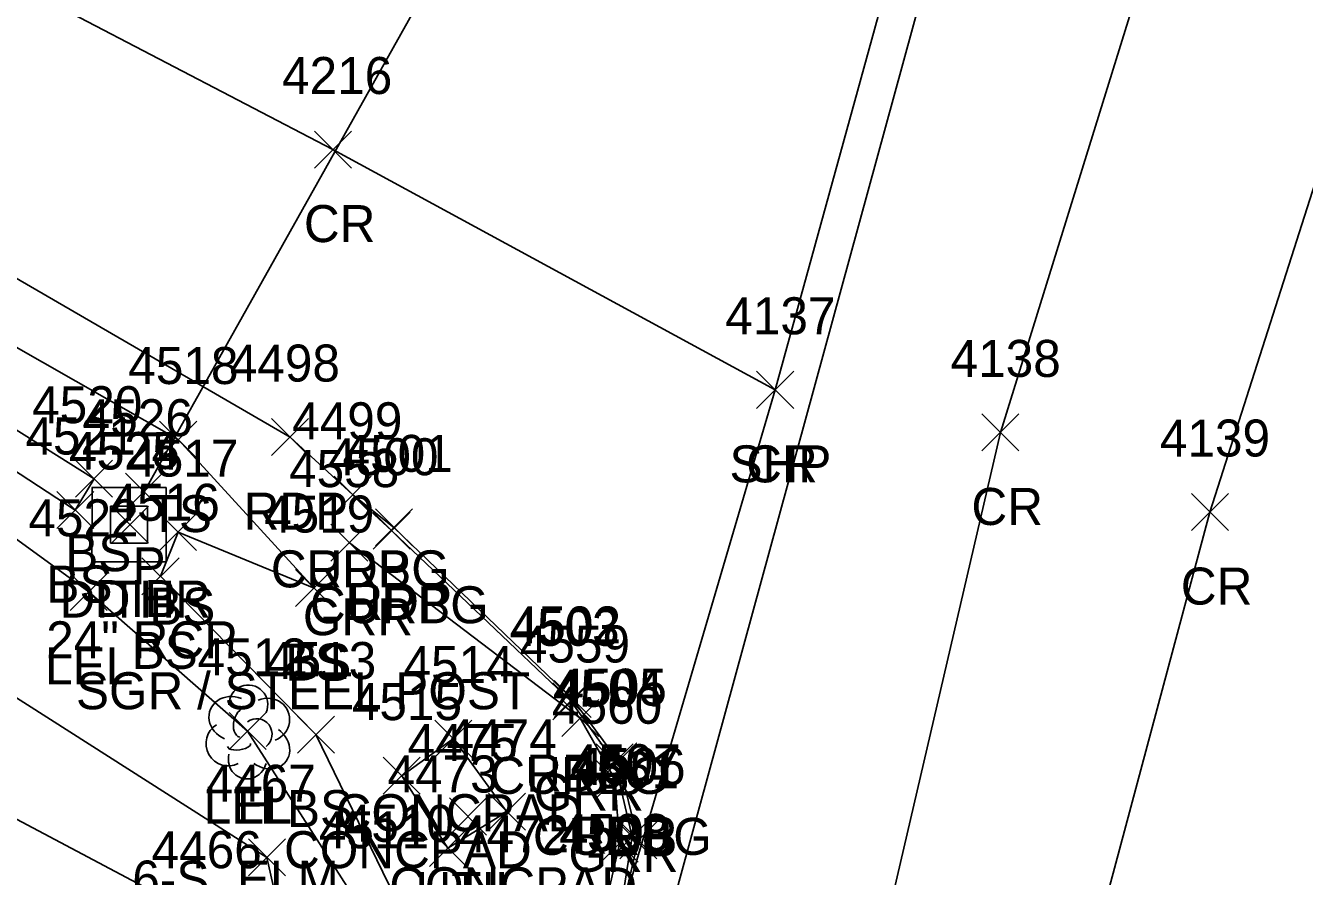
# Model space of a CAD drawing. Extents: x 1462089 to 1464015, y 730534 to 736144.
# Drawn here: x 1462683.9 to 1462752.9, y 731897.3 to 731943.3 of the extents above; entities that cross this region are included whole.
import ezdxf

# ---------------------------------------------------------------- set-up
doc = ezdxf.new("R2010")
doc.units = 0
for name, color, linetype in [('D_A', 7, 'Continuous'), ('D_C', 7, 'Continuous'), ('D_I', 7, 'Continuous'), ('D_TIC', 7, 'Continuous'), ('DCP', 7, 'Continuous'), ('DS', 7, 'Continuous'), ('L_A', 7, 'Continuous'), ('L_C', 7, 'Continuous'), ('L_I', 7, 'Continuous'), ('L_TIC', 7, 'Continuous'), ('LARO', 7, 'Continuous'), ('LELB', 7, 'Continuous'), ('LS', 7, 'Continuous'), ('LTD', 7, 'Continuous'), ('P_A', 7, 'Continuous'), ('P_I', 7, 'Continuous'), ('P_TIC', 7, 'Continuous'), ('PET', 7, 'Continuous'), ('PRC', 7, 'Continuous'), ('PSP', 7, 'Continuous'), ('R_A', 7, 'Continuous'), ('R_C', 7, 'Continuous'), ('R_I', 7, 'Continuous'), ('R_TIC', 7, 'Continuous'), ('RC', 7, 'Continuous'), ('RGR', 7, 'Continuous'), ('U_A', 7, 'Continuous'), ('U_I', 7, 'Continuous'), ('UDEFAULT', 7, 'Continuous')]:
    doc.layers.add(name, color=color, linetype=linetype)

msp = doc.modelspace()

# ---------------------------------------------------------------- linework, layer by layer
at = {"layer": 'D_TIC'}
for points in [[(1462689.278, 731917.109), (1462691.278, 731919.109)], [(1462691.278, 731917.109), (1462689.278, 731919.109)], [(1462688.512, 731915.337), (1462690.512, 731917.337)], [(1462690.512, 731915.337), (1462688.512, 731917.337)]]:
    msp.add_lwpolyline(points, dxfattribs=at)
at = {"layer": 'DCP'}
msp.add_lwpolyline([(1462690.278, 731918.109), (1462711.608, 731956.178)], dxfattribs=at)
at = {"layer": 'DS'}
for p, q in [((1462687.467, 731918.331), (1462691.467, 731918.331)), ((1462687.467, 731914.331), (1462687.478, 731918.331)), ((1462691.467, 731918.331), (1462691.467, 731914.331)), ((1462688.467, 731917.331), (1462690.467, 731917.331)), ((1462688.467, 731915.331), (1462688.467, 731917.331)), ((1462690.467, 731917.331), (1462690.467, 731915.331)), ((1462689.47, 731916.341), (1462689.47, 731916.341)), ((1462690.467, 731915.331), (1462688.467, 731915.331)), ((1462691.467, 731914.331), (1462687.467, 731914.331)), ((1462689.967, 731914.331), (1462690.467, 731914.331))]:
    msp.add_line(p, q, dxfattribs=at)
at = {"layer": 'L_TIC'}
for points in [[(1462691.118, 731919.928), (1462693.118, 731921.928)], [(1462693.118, 731919.928), (1462691.118, 731921.928)], [(1462686.582, 731917.813), (1462688.582, 731919.813)], [(1462688.582, 731917.813), (1462686.582, 731919.813)], [(1462685.566, 731916.121), (1462687.566, 731918.121)], [(1462687.566, 731916.121), (1462685.566, 731918.121)], [(1462685.566, 731916.121), (1462687.566, 731918.121)], [(1462687.566, 731916.121), (1462685.566, 731918.121)], [(1462691.115, 731914.927), (1462693.115, 731916.927)], [(1462693.115, 731914.927), (1462691.115, 731916.927)], [(1462690.165, 731912.54), (1462692.165, 731914.54)], [(1462692.165, 731912.54), (1462690.165, 731914.54)], [(1462686.293, 731911.7), (1462688.293, 731913.7)], [(1462688.293, 731911.7), (1462686.293, 731913.7)], [(1462698.457, 731911.905), (1462700.457, 731913.905)], [(1462700.457, 731911.905), (1462698.457, 731913.905)], [(1462698.457, 731911.905), (1462700.457, 731913.905)], [(1462700.457, 731911.905), (1462698.457, 731913.905)], [(1462694.863, 731904.182), (1462696.863, 731906.182)], [(1462696.863, 731904.182), (1462694.863, 731906.182)], [(1462698.554, 731903.99), (1462700.554, 731905.99)], [(1462700.554, 731903.99), (1462698.554, 731905.99)], [(1462705.975, 731903.769), (1462707.975, 731905.769)], [(1462707.975, 731903.769), (1462705.975, 731905.769)], [(1462703.187, 731901.769), (1462705.187, 731903.769)], [(1462705.187, 731901.769), (1462703.187, 731903.769)], [(1462703.187, 731901.769), (1462705.187, 731903.769)], [(1462705.187, 731901.769), (1462703.187, 731903.769)], [(1462708.87, 731899.82), (1462710.87, 731901.82)], [(1462710.87, 731899.82), (1462708.87, 731901.82)], [(1462705.679, 731897.86), (1462707.679, 731899.86)], [(1462707.679, 731897.86), (1462705.679, 731899.86)], [(1462705.679, 731897.86), (1462707.679, 731899.86)], [(1462707.679, 731897.86), (1462705.679, 731899.86)], [(1462695.908, 731897.356), (1462697.908, 731899.356)], [(1462697.908, 731897.356), (1462695.908, 731899.356)]]:
    msp.add_lwpolyline(points, dxfattribs=at)
at = {"layer": 'LARO'}
msp.add_lwpolyline([(1462589.808, 731946.268), (1462608.55, 731942.119), (1462643.504, 731922.201), (1462657.732, 731918.487), (1462679.228, 731902.613), (1462694.044, 731894.769), (1462699.116, 731888.563), (1462702.71, 731886.196), (1462701.841, 731895.851), (1462695.863, 731905.182), (1462687.293, 731912.7), (1462675.532, 731921.259)], dxfattribs=at)
at = {"layer": 'LELB'}
for points in [[(1462268.94, 732149.282), (1462308.429, 732128.708), (1462354.326, 732103.889), (1462394.145, 732084.385), (1462412.358, 732075.221), (1462457.636, 732049.358), (1462490.941, 732032.421), (1462529.697, 732010.667), (1462568.834, 731990.726), (1462593.622, 731976.788), (1462623.592, 731959.995), (1462654.366, 731942.73), (1462672.05, 731932.373), (1462692.118, 731920.928), (1462699.457, 731912.905)], [(1462266.761, 732145.227), (1462282.115, 732139.32), (1462308.304, 732126.234), (1462353.11, 732101.185), (1462392.774, 732082.131), (1462409.999, 732072.544), (1462437.812, 732058.163), (1462456.098, 732047.415), (1462489.733, 732029.297), (1462527.827, 732008.415), (1462565.396, 731986.637), (1462591.353, 731974.348), (1462620.094, 731957.414), (1462653.178, 731940.628), (1462669.351, 731930.264), (1462687.582, 731918.813), (1462686.566, 731917.121)], [(1462265.409, 732143.181), (1462280.797, 732137.454), (1462306.416, 732125.033), (1462332.729, 732110.486), (1462352.666, 732099.709), (1462392.045, 732079.225), (1462401.617, 732073.615), (1462408.504, 732070.133), (1462436.184, 732056.009), (1462454.76, 732045.376), (1462489.042, 732027.17), (1462528.857, 732005.668), (1462564.821, 731983.978), (1462590.193, 731972.528), (1462609.628, 731960.712), (1462619.797, 731955.248), (1462652.264, 731939.113), (1462668.145, 731929.165), (1462686.566, 731917.121)], [(1462608.197, 731946.492), (1462648.041, 731929.151), (1462659.901, 731925.742), (1462680.838, 731908.603), (1462696.908, 731898.356), (1462699.116, 731888.563)], [(1462698.466, 731855.117), (1462701.841, 731881.137), (1462702.71, 731886.196), (1462703.836, 731896.195), (1462699.554, 731904.99), (1462691.165, 731913.54), (1462692.115, 731915.927), (1462699.457, 731912.905)]]:
    msp.add_lwpolyline(points, dxfattribs=at)
at = {"layer": 'LS'}
for points in [[(1462706.679, 731898.86), (1462709.87, 731900.82), (1462706.975, 731904.769), (1462704.187, 731902.769)], [(1462706.679, 731898.86), (1462704.187, 731902.769)]]:
    msp.add_lwpolyline(points, dxfattribs=at)
at = {"layer": 'LTD'}
msp.add_line((1462695.863, 731905.182), (1462695.863, 731905.182), dxfattribs=at)
msp.add_line((1462695.863, 731905.182), (1462695.863, 731905.182), dxfattribs=at)
msp.add_arc((1462695.909, 731906.616), 1.047, 335.52715, 180.95627, dxfattribs=at)
for centre, major_axis, ratio, start_param, end_param in [((1462695.071, 731905.848), (1.21, -0.512), 0.895232, 1.570796, 4.712389), ((1462696.904, 731905.765), (-1.141, -0.483), 0.949671, 1.570796, 4.712389), ((1462695.654, 731905.64), (-0.208, -0.792), 0.645439, 3.141593, 6.283185), ((1462696.363, 731905.015), (-0.5, 0.667), 0.989748, 3.141593, 6.283185), ((1462694.779, 731904.473), (0.584, -1.042), 0.959034, 3.141593, 6.283185), ((1462696.863, 731904.349), (-1.09, 0.792), 0.841452, 1.570796, 4.712389), ((1462695.404, 731904.432), (-0.625, -0.083), 0.423636, 0, 3.141593), ((1462695.863, 731903.682), (0.265, 1.061), 0.942809, 1.570796, 4.712389)]:
    msp.add_ellipse(centre, major_axis=major_axis, ratio=ratio, start_param=start_param, end_param=end_param, dxfattribs=at)
at = {"layer": 'P_TIC'}
for points in [[(1462699.474, 731935.597), (1462701.474, 731937.597)], [(1462701.474, 731935.597), (1462699.474, 731937.597)], [(1462723.347, 731922.615), (1462725.347, 731924.615)], [(1462725.347, 731922.615), (1462723.347, 731924.615)], [(1462723.347, 731922.615), (1462725.347, 731924.615)], [(1462725.347, 731922.615), (1462723.347, 731924.615)], [(1462735.508, 731920.312), (1462737.508, 731922.312)], [(1462737.508, 731920.312), (1462735.508, 731922.312)], [(1462697.163, 731920.062), (1462699.163, 731922.062)], [(1462699.163, 731920.062), (1462697.163, 731922.062)], [(1462700.54, 731916.942), (1462702.54, 731918.942)], [(1462702.54, 731916.942), (1462700.54, 731918.942)], [(1462746.813, 731916.011), (1462748.813, 731918.011)], [(1462748.813, 731916.011), (1462746.813, 731918.011)], [(1462702.764, 731915.183), (1462704.764, 731917.183)], [(1462704.764, 731915.183), (1462702.764, 731917.183)], [(1462712.414, 731905.911), (1462714.414, 731907.911)], [(1462714.414, 731905.911), (1462712.414, 731907.911)], [(1462714.886, 731902.55), (1462716.886, 731904.55)], [(1462716.886, 731902.55), (1462714.886, 731904.55)], [(1462715.954, 731898.27), (1462717.954, 731900.27)], [(1462717.954, 731898.27), (1462715.954, 731900.27)]]:
    msp.add_lwpolyline(points, dxfattribs=at)
at = {"layer": 'PET'}
for points in [[(1462270.446, 732152.098), (1462310.215, 732132.266), (1462357.014, 732107.798), (1462395.932, 732087.15), (1462413.045, 732077.52), (1462458.622, 732052.137), (1462491.931, 732034.249), (1462531.048, 732012.558), (1462569.662, 731992.168), (1462594.884, 731978.539), (1462624.97, 731962.023), (1462656.05, 731945.195), (1462673.713, 731935.253), (1462698.163, 731921.062), (1462701.54, 731917.942), (1462703.764, 731916.183), (1462713.414, 731906.911), (1462715.886, 731903.55), (1462716.954, 731899.27), (1462716.132, 731895.689)], [(1462737.297, 731963.429), (1462717.097, 731889.531), (1462708.571, 731860.874), (1462695.151, 731815.712), (1462691.036, 731802.029), (1462676.866, 731754.297), (1462666.22, 731719.346), (1462652.4, 731671.376), (1462641.384, 731635.734), (1462629.681, 731597.191), (1462612.657, 731543.575), (1462596.763, 731494.09), (1462582.573, 731446.883), (1462571.372, 731410.944), (1462559.842, 731372.737), (1462542.966, 731314.951), (1462524.38, 731258.465), (1462511.655, 731215.872), (1462491.671, 731142.677)]]:
    msp.add_lwpolyline(points, dxfattribs=at)
at = {"layer": 'PRC'}
for points in [[(1462724.347, 731923.615), (1462700.474, 731936.597), (1462662.876, 731956.214), (1462633.35, 731971.357), (1462598.489, 731991.214), (1462563.004, 732009.777), (1462522.464, 732031.762), (1462486.74, 732050.761), (1462447.614, 732072.427), (1462416.617, 732089.421), (1462381.133, 732108.666), (1462345.698, 732127.482), (1462314.565, 732143.615), (1462276.113, 732162.808)], [(1462748.947, 731961.516), (1462736.508, 731921.312), (1462728.403, 731886.375), (1462719.051, 731858.42), (1462705.389, 731810.89), (1462700.841, 731800.166), (1462687.609, 731751.705), (1462676.23, 731715.789), (1462662.619, 731667.958), (1462651.175, 731633.325), (1462639.174, 731589.059), (1462623.338, 731538.877), (1462607.5, 731490.665), (1462593.428, 731442.927), (1462581.597, 731409.026), (1462569.166, 731365.289), (1462553.746, 731313.655), (1462535.681, 731254.443), (1462519.258, 731196.564), (1462502.241, 731140.649), (1462491.591, 731093.412)], [(1462761.024, 731958.42), (1462747.813, 731917.011), (1462738.765, 731883.168), (1462729.105, 731854.955), (1462715.075, 731806.479), (1462712.125, 731796.984), (1462698.106, 731749.334), (1462686.279, 731711.956), (1462673.041, 731665.233), (1462661.991, 731629.565), (1462648.473, 731585.76), (1462633.362, 731535.924), (1462617.816, 731486.899), (1462603.279, 731439.323), (1462592.214, 731404.808), (1462578.747, 731359.841), (1462563.848, 731311.635), (1462546.163, 731252.054), (1462529.312, 731193.323), (1462512.831, 731138.457), (1462500.459, 731089.177), (1462489.909, 731049.965), (1462473.447, 730997.549), (1462460.794, 730938.782)]]:
    msp.add_lwpolyline(points, dxfattribs=at)
at = {"layer": 'PSP'}
msp.add_lwpolyline([(1462735.883, 731965.543), (1462724.347, 731923.615), (1462716.132, 731895.689), (1462706.261, 731861.752), (1462701.796, 731847.13), (1462699.466, 731840.009), (1462692.812, 731817.612), (1462688.624, 731803.324), (1462674.431, 731755.229), (1462670.575, 731742.725), (1462669.096, 731737.252), (1462663.062, 731716.697), (1462649.924, 731672.978), (1462639.27, 731636.282), (1462627.328, 731597.087), (1462624.657, 731584.618), (1462611.691, 731544.088), (1462595.98, 731494.281), (1462581.441, 731447.372), (1462570.158, 731410.408), (1462558.82, 731372.899), (1462541.297, 731315.135), (1462524.38, 731258.465)], dxfattribs=at)
at = {"layer": 'R_TIC'}
for points in [[(1462700.54, 731916.942), (1462702.54, 731918.942)], [(1462702.54, 731916.942), (1462700.54, 731918.942)], [(1462702.646, 731915.001), (1462704.646, 731917.001)], [(1462704.646, 731915.001), (1462702.646, 731917.001)], [(1462700.364, 731914.357), (1462702.364, 731916.357)], [(1462702.364, 731914.357), (1462700.364, 731916.357)], [(1462712.336, 731905.783), (1462714.336, 731907.783)], [(1462714.336, 731905.783), (1462712.336, 731907.783)], [(1462712.829, 731904.882), (1462714.829, 731906.882)], [(1462714.829, 731904.882), (1462712.829, 731906.882)], [(1462714.685, 731902.489), (1462716.685, 731904.489)], [(1462716.685, 731902.489), (1462714.685, 731904.489)], [(1462714.694, 731901.572), (1462716.694, 731903.572)], [(1462716.694, 731901.572), (1462714.694, 731903.572)], [(1462715.636, 731898.468), (1462717.636, 731900.468)], [(1462717.636, 731898.468), (1462715.636, 731900.468)], [(1462714.944, 731898.09), (1462716.944, 731900.09)], [(1462716.944, 731898.09), (1462714.944, 731900.09)]]:
    msp.add_lwpolyline(points, dxfattribs=at)
at = {"layer": 'RC'}
msp.add_lwpolyline([(1462701.54, 731917.942), (1462703.646, 731916.001), (1462713.336, 731906.783), (1462715.685, 731903.489), (1462716.636, 731899.468), (1462716.029, 731895.702), (1462705.947, 731861.622), (1462701.64, 731847.229), (1462699.466, 731840.009)], dxfattribs=at)
at = {"layer": 'RGR'}
msp.add_lwpolyline([(1462701.364, 731915.357), (1462713.829, 731905.882), (1462715.694, 731902.572), (1462715.944, 731899.09), (1462713.944, 731890.347), (1462704.68, 731859.614), (1462700.958, 731847.398), (1462699.27, 731840.124), (1462692.812, 731817.612)], dxfattribs=at)
at = {"layer": 'UDEFAULT'}
for points in [[(1462706.765, 731899.563), (1462708.765, 731901.563)], [(1462708.765, 731899.563), (1462706.765, 731901.563)]]:
    msp.add_lwpolyline(points, dxfattribs=at)

# ---------------------------------------------------------------- texts
at = {"layer": 'D_A'}
for s, p in [('P', (1462689.656, 731913.109)), ('DITHR', (1462685.714, 731911.31)), ('DIB', (1462687.614, 731911.337))]:
    msp.add_text(s, height=2, dxfattribs=at).set_placement(p)
at = {"layer": 'D_C'}
msp.add_text('24" RCP', height=2, dxfattribs=at).set_placement((1462684.995, 731909.109))
at = {"layer": 'D_I'}
for s, p in [('4526', (1462686.964, 731921.109)), ('4524', (1462686.226, 731919.31)), ('4525', (1462686.252, 731919.337))]:
    msp.add_text(s, height=2, dxfattribs=at).set_placement(p)
at = {"layer": 'L_A'}
for s, p in [('TS', (1462690.528, 731915.928)), ('BS', (1462686.023, 731913.813)), ('BS', (1462685.007, 731912.121)), ('BS', (1462685.007, 731912.121)), ('BS', (1462690.556, 731910.927)), ('BS', (1462689.606, 731908.54)), ('TS', (1462697.867, 731907.905)), ('BS', (1462697.898, 731907.905)), ('LEL', (1462684.931, 731907.7)), ('LEL', (1462693.5, 731900.182)), ('H', (1462695.296, 731900.182)), ('BS', (1462697.995, 731899.99)), ('CONCPAD', (1462700.621, 731899.769)), ('CONCPAD', (1462697.832, 731897.769)), ('CONCPAD', (1462697.832, 731897.769)), ('CONCPAD', (1462703.515, 731895.82))]:
    msp.add_text(s, height=2, dxfattribs=at).set_placement(p)
at = {"layer": 'L_C'}
msp.add_text('6-S. ELM', height=2, dxfattribs=at).set_placement((1462689.642, 731896.182))
at = {"layer": 'L_I'}
for s, p in [('4518', (1462689.425, 731923.928)), ('4520', (1462684.235, 731921.813)), ('4521', (1462683.873, 731920.121)), ('4521', (1462683.873, 731920.121)), ('4517', (1462689.422, 731918.927)), ('4516', (1462688.417, 731916.54)), ('4522', (1462684.033, 731915.7)), ('4519', (1462696.757, 731915.905)), ('4519', (1462696.757, 731915.905)), ('4512', (1462693.17, 731908.182)), ('4512', (1462693.17, 731908.182)), ('4513', (1462696.861, 731907.99)), ('4514', (1462704.282, 731907.769)), ('4515', (1462701.494, 731905.769)), ('4515', (1462701.494, 731905.769)), ('4474', (1462706.61, 731903.82)), ('4473', (1462703.419, 731901.86)), ('4473', (1462703.419, 731901.86)), ('4467', (1462693.601, 731901.356)), ('4511', (1462699.715, 731898.851)), ('4510', (1462701.057, 731899.195)), ('4466', (1462690.682, 731897.769))]:
    msp.add_text(s, height=2, dxfattribs=at).set_placement(p)
at = {"layer": 'P_A'}
for s, p in [('CR', (1462698.907, 731931.597)), ('SHP', (1462721.882, 731918.615)), ('CR', (1462722.78, 731918.615)), ('CR', (1462734.941, 731916.312)), ('RDP', (1462695.651, 731916.062)), ('RDP', (1462699.028, 731912.942)), ('CR', (1462746.246, 731912.011)), ('RDP', (1462701.252, 731911.183)), ('RDP', (1462710.902, 731901.911)), ('RDP', (1462713.374, 731898.55))]:
    msp.add_text(s, height=2, dxfattribs=at).set_placement(p)
at = {"layer": 'P_I'}
for s, p in [('4216', (1462697.726, 731939.597)), ('4137', (1462721.654, 731926.615)), ('4137', (1462721.654, 731926.615)), ('4498', (1462694.903, 731924.062)), ('4138', (1462733.816, 731924.312)), ('4499', (1462698.272, 731920.942)), ('4139', (1462745.113, 731920.011)), ('4501', (1462700.992, 731919.183)), ('4502', (1462710.075, 731909.911)), ('4505', (1462712.548, 731906.55)), ('4506', (1462713.561, 731902.27)), ('4509', (1462712.786, 731898.689)), ('4509', (1462712.786, 731898.689))]:
    msp.add_text(s, height=2, dxfattribs=at).set_placement(p)
at = {"layer": 'R_A'}
for s, p in [('CURBG', (1462697.123, 731912.942)), ('CURBG', (1462699.229, 731911.001)), ('GRR', (1462698.852, 731910.357)), ('CURBG', (1462708.919, 731901.783)), ('GRR', (1462711.317, 731900.882)), ('CURBG', (1462711.268, 731898.489)), ('GRR', (1462713.182, 731897.572))]:
    msp.add_text(s, height=2, dxfattribs=at).set_placement(p)
at = {"layer": 'R_C'}
msp.add_text('SGR / STEEL POST', height=2, dxfattribs=at).set_placement((1462686.601, 731906.357))
at = {"layer": 'R_I'}
for s, p in [('4499', (1462698.272, 731920.942)), ('4500', (1462700.221, 731919.001)), ('4558', (1462698.104, 731918.357)), ('4503', (1462709.998, 731909.783)), ('4559', (1462710.562, 731908.882)), ('4504', (1462712.347, 731906.489)), ('4560', (1462712.3, 731905.572)), ('4507', (1462713.298, 731902.468)), ('4561', (1462713.204, 731902.09)), ('4508', (1462712.691, 731898.702))]:
    msp.add_text(s, height=2, dxfattribs=at).set_placement(p)
at = {"layer": 'U_A'}
msp.add_text('UTIL', height=2, dxfattribs=at).set_placement((1462704.931, 731895.563))
at = {"layer": 'U_I'}
for s, p in [('4475', (1462704.506, 731903.563)), ('4472', (1462707.278, 731898.626))]:
    msp.add_text(s, height=2, dxfattribs=at).set_placement(p)

doc.saveas('drawing.dxf')
